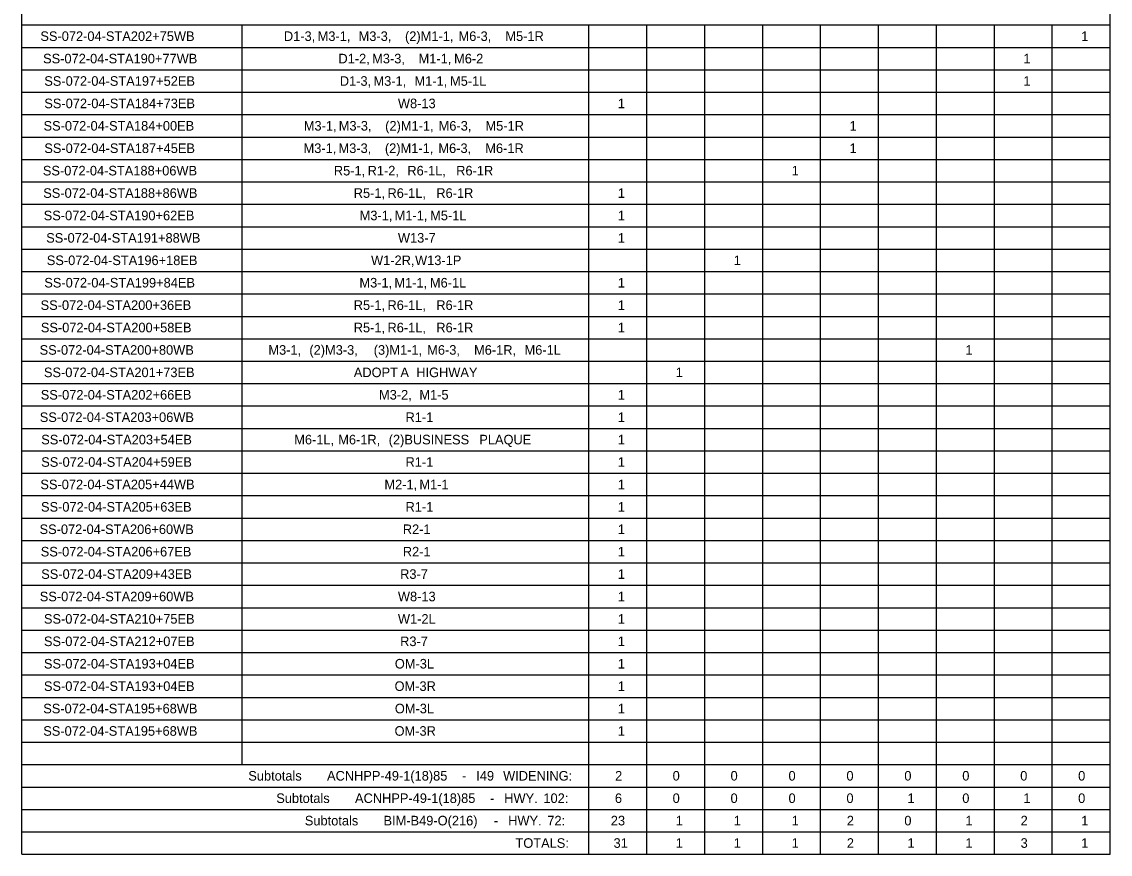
# Model space of a CAD drawing. Extents: x 1226613 to 1228135, y 151309 to 152326.
# Drawn here: x 1227562 to 1228073, y 151550 to 151941 of the extents above; entities that cross this region are included whole.
import ezdxf

# ---------------------------------------------------------------- set-up
doc = ezdxf.new("R2010")
doc.units = 0
doc.layers.add('R_Dimension', color=7, linetype='Continuous')

msp = doc.modelspace()

# ---------------------------------------------------------------- linework, layer by layer
at = {"layer": 'R_Dimension'}
for p, q in [((1227562.3, 151549.57), (1227562.3, 152118.19)), ((1228073.44, 151549.57), (1228073.44, 152118.19)), ((1227562.3, 151939.18), (1228073.44, 151939.18)), ((1227665.84, 151591.69), (1227665.84, 151939.18)), ((1227828.62, 151549.57), (1227828.62, 151939.18)), ((1227855.82, 151549.57), (1227855.82, 151939.18)), ((1227883.02, 151549.57), (1227883.02, 151939.18)), ((1227910.23, 151549.57), (1227910.23, 151939.18)), ((1227937.43, 151549.57), (1227937.43, 151939.18)), ((1227964.63, 151549.57), (1227964.63, 151939.18)), ((1227991.83, 151549.57), (1227991.83, 151939.18)), ((1228019.04, 151549.57), (1228019.04, 151939.18)), ((1228046.24, 151549.57), (1228046.24, 151939.18)), ((1227562.3, 151928.65), (1228073.44, 151928.65)), ((1227562.3, 151918.12), (1228073.44, 151918.12)), ((1227562.3, 151907.59), (1228073.44, 151907.59)), ((1227562.3, 151897.06), (1228073.44, 151897.06)), ((1227562.3, 151886.53), (1228073.44, 151886.53)), ((1227562.3, 151876), (1228073.44, 151876)), ((1227562.3, 151865.47), (1228073.44, 151865.47)), ((1227562.3, 151854.94), (1228073.44, 151854.94)), ((1227562.3, 151844.41), (1228073.44, 151844.41)), ((1227562.3, 151833.88), (1228073.44, 151833.88)), ((1227562.3, 151823.35), (1228073.44, 151823.35)), ((1227562.3, 151812.82), (1228073.44, 151812.82)), ((1227562.3, 151802.29), (1228073.44, 151802.29)), ((1227562.3, 151791.76), (1228073.44, 151791.76)), ((1227562.3, 151781.23), (1228073.44, 151781.23)), ((1227562.3, 151770.7), (1228073.44, 151770.7)), ((1227562.3, 151760.17), (1228073.44, 151760.17)), ((1227562.3, 151749.64), (1228073.44, 151749.64)), ((1227562.3, 151739.11), (1228073.44, 151739.11)), ((1227562.3, 151728.58), (1228073.44, 151728.58)), ((1227562.3, 151718.05), (1228073.44, 151718.05)), ((1227562.3, 151707.52), (1228073.44, 151707.52)), ((1227562.3, 151696.99), (1228073.44, 151696.99)), ((1227562.3, 151686.46), (1228073.44, 151686.46)), ((1227562.3, 151675.93), (1228073.44, 151675.93)), ((1227562.3, 151665.4), (1228073.44, 151665.4)), ((1227562.3, 151654.87), (1228073.44, 151654.87)), ((1227562.3, 151644.34), (1228073.44, 151644.34)), ((1227562.3, 151633.81), (1228073.44, 151633.81)), ((1227562.3, 151623.28), (1228073.44, 151623.28)), ((1227562.3, 151612.75), (1228073.44, 151612.75)), ((1227562.3, 151602.22), (1228073.44, 151602.22)), ((1227562.3, 151591.69), (1228073.44, 151591.69)), ((1227562.3, 151581.16), (1228073.44, 151581.16)), ((1227562.3, 151570.63), (1228073.44, 151570.63)), ((1227562.3, 151560.1), (1228073.44, 151560.1)), ((1227562.3, 151549.57), (1228073.44, 151549.57))]:
    msp.add_line(p, q, dxfattribs=at)

# ---------------------------------------------------------------- texts
for s, p in [('SS-072-04-STA202+75WB', (1227571.04, 151931.67)), ('D1-3,', (1227685.4, 151931.67)), (' M3-1,', (1227699.57, 151931.67)), (' M3-3,', (1227718.81, 151931.67)), (' (2)M1-1,', (1227740.6, 151931.67)), (' M6-3,', (1227765.73, 151931.67)), (' M5-1R', (1227787.73, 151931.67)), ('1', (1228059.84, 151931.67)), ('SS-072-04-STA190+77WB', (1227572.31, 151921.14)), ('D1-2,', (1227711, 151921.14)), (' M3-3,', (1227725.17, 151921.14)), (' M1-1,', (1227746.97, 151921.14)), (' M6-2', (1227763.65, 151921.14)), ('1', (1228032.64, 151921.14)), ('SS-072-04-STA197+52EB', (1227572.88, 151910.61)), ('D1-3,', (1227711.64, 151910.61)), (' M3-1,', (1227725.81, 151910.61)), (' M1-1,', (1227745.05, 151910.61)), (' M5-1L', (1227761.74, 151910.61)), ('1', (1228032.64, 151910.61)), ('SS-072-04-STA184+73EB', (1227572.88, 151900.08)), ('W8-13', (1227738.94, 151900.08)), ('1', (1227842.22, 151900.08)), ('SS-072-04-STA184+00EB', (1227572.52, 151889.55)), ('M3-1,', (1227694.74, 151889.55)), (' M3-3,', (1227709.48, 151889.55)), (' (2)M1-1,', (1227731.27, 151889.55)), (' M6-3,', (1227756.39, 151889.55)), (' M5-1R', (1227778.39, 151889.55)), ('1', (1227951.03, 151889.55)), ('SS-072-04-STA187+45EB', (1227572.88, 151879.02)), ('M3-1,', (1227694.63, 151879.02)), (' M3-3,', (1227709.37, 151879.02)), (' (2)M1-1,', (1227731.16, 151879.02)), (' M6-3,', (1227756.28, 151879.02)), (' M6-1R', (1227778.29, 151879.02)), ('1', (1227951.03, 151879.02)), ('SS-072-04-STA188+06WB', (1227572.21, 151868.49)), ('R5-1,', (1227708.86, 151868.49)), (' R1-2,', (1227723.03, 151868.49)), (' R6-1L,', (1227741.7, 151868.49)), (' R6-1R', (1227764.63, 151868.49)), ('1', (1227923.83, 151868.49)), ('SS-072-04-STA188+86WB', (1227572.38, 151857.96)), ('R5-1,', (1227718.19, 151857.96)), (' R6-1L,', (1227732.37, 151857.96)), (' R6-1R', (1227755.29, 151857.96)), ('1', (1227842.22, 151857.96)), ('SS-072-04-STA190+62EB', (1227572.6, 151847.43)), ('M3-1,', (1227720.97, 151847.43)), (' M1-1,', (1227735.72, 151847.43)), (' M5-1L', (1227752.4, 151847.43)), ('1', (1227842.22, 151847.43)), ('SS-072-04-STA191+88WB', (1227573.77, 151836.9)), ('W13-7', (1227738.94, 151836.9)), ('1', (1227842.22, 151836.9)), ('SS-072-04-STA196+18EB', (1227574.05, 151826.37)), ('W1-2R,', (1227726.33, 151826.37)), (' W13-1P', (1227745.32, 151826.37)), ('1', (1227896.63, 151826.37)), ('SS-072-04-STA199+84EB', (1227572.88, 151815.84)), ('M3-1,', (1227720.87, 151815.84)), (' M1-1,', (1227735.61, 151815.84)), (' M6-1L', (1227752.3, 151815.84)), ('1', (1227842.22, 151815.84)), ('SS-072-04-STA200+36EB', (1227571.14, 151805.31)), ('R5-1,', (1227718.19, 151805.31)), (' R6-1L,', (1227732.37, 151805.31)), (' R6-1R', (1227755.29, 151805.31)), ('1', (1227842.22, 151805.31)), ('SS-072-04-STA200+58EB', (1227571.25, 151794.78)), ('R5-1,', (1227718.19, 151794.78)), (' R6-1L,', (1227732.37, 151794.78)), (' R6-1R', (1227755.29, 151794.78)), ('1', (1227842.22, 151794.78)), ('SS-072-04-STA200+80WB', (1227570.68, 151784.25)), (' M3-1,', (1227676.44, 151784.25)), (' (2)M3-3,', (1227695.68, 151784.25)), (' (3)M1-1,', (1227725.9, 151784.25)), (' M6-3,', (1227751.02, 151784.25)), (' M6-1R,', (1227773.03, 151784.25)), (' M6-1L', (1227796.73, 151784.25)), ('1', (1228005.44, 151784.25)), ('SS-072-04-STA201+73EB', (1227572.7, 151773.72)), ('ADOPT', (1227718.21, 151773.72)), (' A', (1227738.44, 151773.72)), (' HIGHWAY', (1227745.88, 151773.72)), ('1', (1227869.42, 151773.72)), ('SS-072-04-STA202+66EB', (1227571.21, 151763.19)), ('M3-2,', (1227730.06, 151763.19)), (' M1-5', (1227747.35, 151763.19)), ('1', (1227842.22, 151763.19)), ('SS-072-04-STA203+06WB', (1227570.75, 151752.66)), ('R1-1', (1227742.52, 151752.66)), ('1', (1227842.22, 151752.66)), ('SS-072-04-STA203+54EB', (1227571.43, 151742.13)), ('M6-1L,', (1227690.24, 151742.13)), (' M6-1R,', (1227709.23, 151742.13)), (' (2)BUSINESS', (1227732.93, 151742.13)), (' PLAQUE', (1227775.49, 151742.13)), ('1', (1227842.22, 151742.13)), ('SS-072-04-STA204+59EB', (1227571.43, 151731.6)), ('R1-1', (1227742.52, 151731.6)), ('1', (1227842.22, 151731.6)), ('SS-072-04-STA205+44WB', (1227571.04, 151721.07)), ('M2-1,', (1227732.61, 151721.07)), (' M1-1', (1227747.35, 151721.07)), ('1', (1227842.22, 151721.07)), ('SS-072-04-STA205+63EB', (1227571.32, 151710.54)), ('R1-1', (1227742.52, 151710.54)), ('1', (1227842.22, 151710.54)), ('SS-072-04-STA206+60WB', (1227570.65, 151700.01)), ('R2-1', (1227741.24, 151700.01)), ('1', (1227842.22, 151700.01)), ('SS-072-04-STA206+67EB', (1227571.21, 151689.48)), ('R2-1', (1227741.24, 151689.48)), ('1', (1227842.22, 151689.48)), ('SS-072-04-STA209+43EB', (1227571.43, 151678.95)), ('R3-7', (1227739.97, 151678.95)), ('1', (1227842.22, 151678.95)), ('SS-072-04-STA209+60WB', (1227570.75, 151668.42)), ('W8-13', (1227738.94, 151668.42)), ('1', (1227842.22, 151668.42)), ('SS-072-04-STA210+75EB', (1227572.7, 151657.89)), ('W1-2L', (1227738.94, 151657.89)), ('1', (1227842.22, 151657.89)), ('SS-072-04-STA212+07EB', (1227572.7, 151647.36)), ('R3-7', (1227739.97, 151647.36)), ('1', (1227842.22, 151647.36)), ('SS-072-04-STA193+04EB', (1227572.7, 151636.83)), ('OM-3L', (1227737.49, 151636.83)), ('1', (1227842.22, 151636.83)), ('SS-072-04-STA193+04EB', (1227572.7, 151626.3)), ('OM-3R', (1227737.36, 151626.3)), ('1', (1227842.22, 151626.3)), ('SS-072-04-STA195+68WB', (1227572.38, 151615.77)), ('OM-3L', (1227737.49, 151615.77)), ('1', (1227842.22, 151615.77)), ('SS-072-04-STA195+68WB', (1227572.38, 151605.24)), ('OM-3R', (1227737.36, 151605.24)), ('1', (1227842.22, 151605.24)), ('Subtotals', (1227668.68, 151584.18)), (' ACNHPP-49-1(18)85', (1227703.97, 151584.18)), (' -', (1227767.36, 151584.18)), (' I49', (1227774.06, 151584.18)), (' WIDENING:', (1227786.67, 151584.18)), ('2', (1227840.94, 151584.18)), ('0', (1227867.95, 151584.18)), ('0', (1227895.15, 151584.18)), ('0', (1227922.36, 151584.18)), ('0', (1227949.56, 151584.18)), ('0', (1227976.76, 151584.18)), ('0', (1228003.96, 151584.18)), ('0', (1228031.17, 151584.18)), ('0', (1228058.37, 151584.18)), ('Subtotals', (1227681.82, 151573.65)), (' ACNHPP-49-1(18)85', (1227717.12, 151573.65)), (' -', (1227780.5, 151573.65)), (' HWY.', (1227787.2, 151573.65)), (' 102:', (1227805.59, 151573.65)), ('6', (1227840.82, 151573.65)), ('0', (1227867.95, 151573.65)), ('0', (1227895.15, 151573.65)), ('0', (1227922.36, 151573.65)), ('0', (1227949.56, 151573.65)), ('1', (1227978.23, 151573.65)), ('0', (1228003.96, 151573.65)), ('1', (1228032.64, 151573.65)), ('0', (1228058.37, 151573.65)), ('Subtotals', (1227695.22, 151563.12)), (' BIM-B49-O(216)', (1227730.51, 151563.12)), (' -', (1227782.35, 151563.12)), (' HWY.', (1227789.04, 151563.12)), (' 72:', (1227807.43, 151563.12)), ('23', (1227838.92, 151563.12)), ('1', (1227869.42, 151563.12)), ('1', (1227896.63, 151563.12)), ('1', (1227923.83, 151563.12)), ('2', (1227949.75, 151563.12)), ('0', (1227976.76, 151563.12)), ('1', (1228005.44, 151563.12)), ('2', (1228031.36, 151563.12)), ('1', (1228059.84, 151563.12)), ('TOTALS:', (1227794.15, 151552.59)), ('31', (1227840.2, 151552.59)), ('1', (1227869.42, 151552.59)), ('1', (1227896.63, 151552.59)), ('1', (1227923.83, 151552.59)), ('2', (1227949.75, 151552.59)), ('1', (1227978.23, 151552.59)), ('1', (1228005.44, 151552.59)), ('3', (1228031.36, 151552.59)), ('1', (1228059.84, 151552.59))]:
    msp.add_text(s, height=4.5, dxfattribs=at).set_placement(p)

doc.saveas('drawing.dxf')
